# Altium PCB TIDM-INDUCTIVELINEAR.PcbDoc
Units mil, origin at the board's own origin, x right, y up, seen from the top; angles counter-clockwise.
Board outline 3600 x 4300 mil, 4 copper layers (Top Layer, Mid-Layer 1, Mid-Layer 2, Bottom Layer), stack 61.2 mil thick; 31 components, 29 nets, 126 pads, 28 vias.
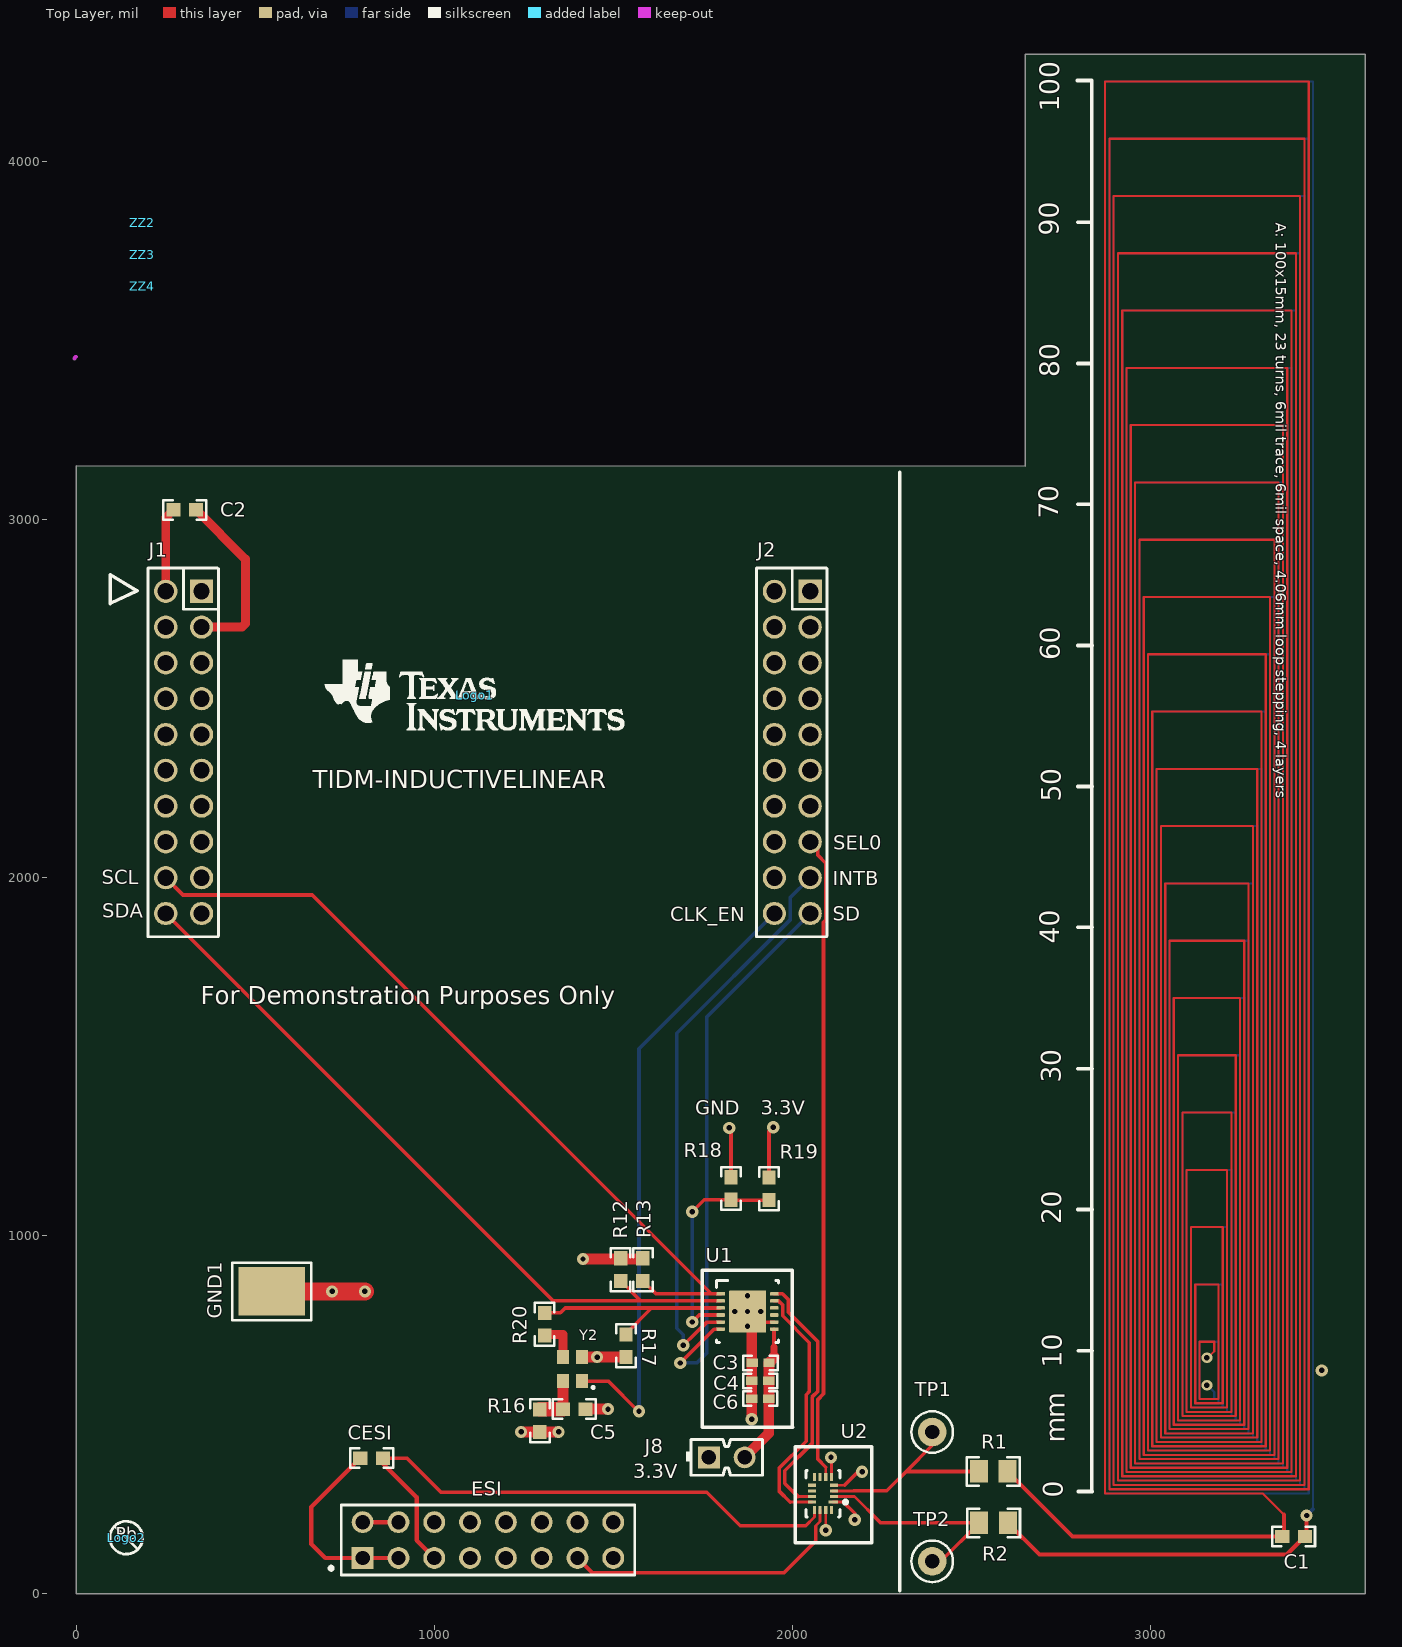
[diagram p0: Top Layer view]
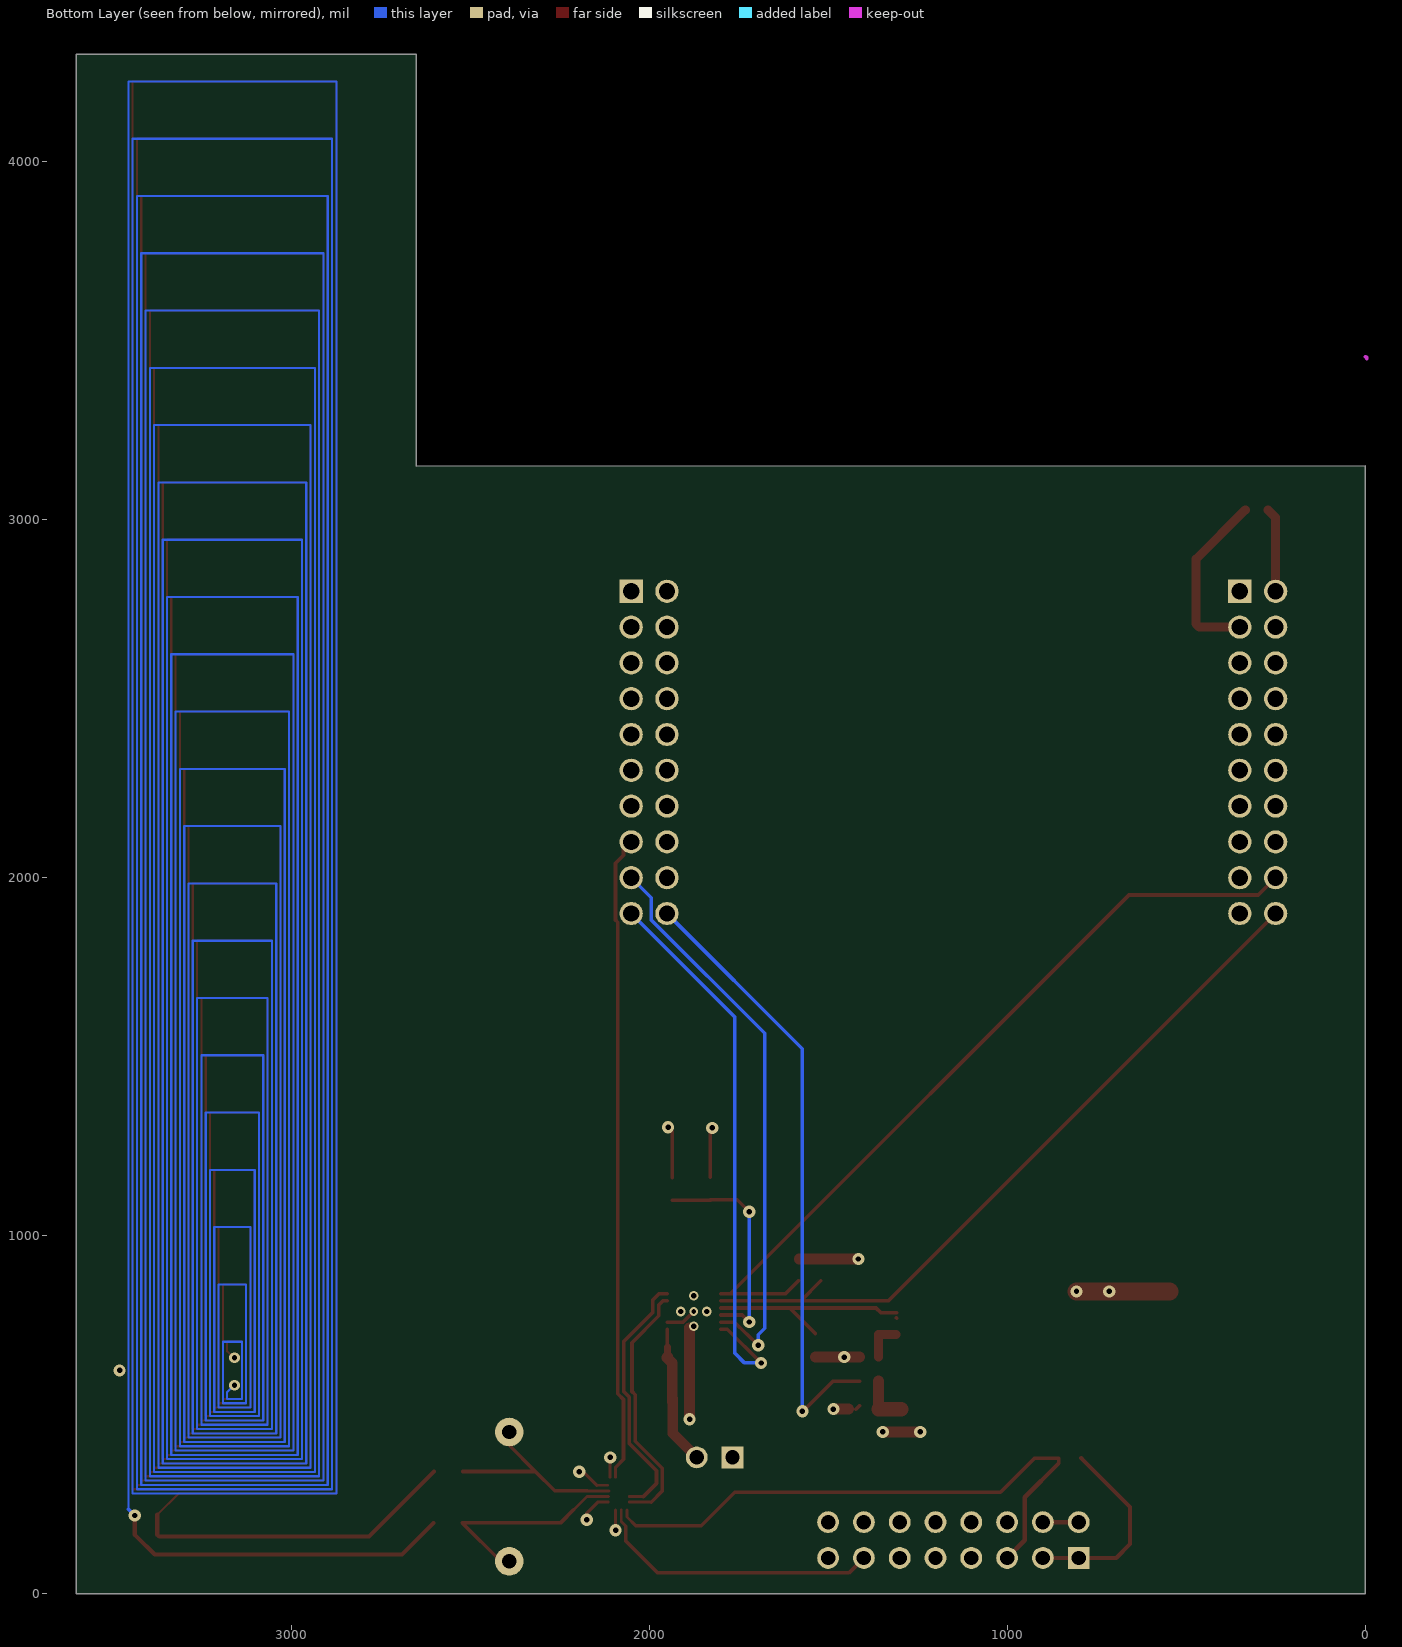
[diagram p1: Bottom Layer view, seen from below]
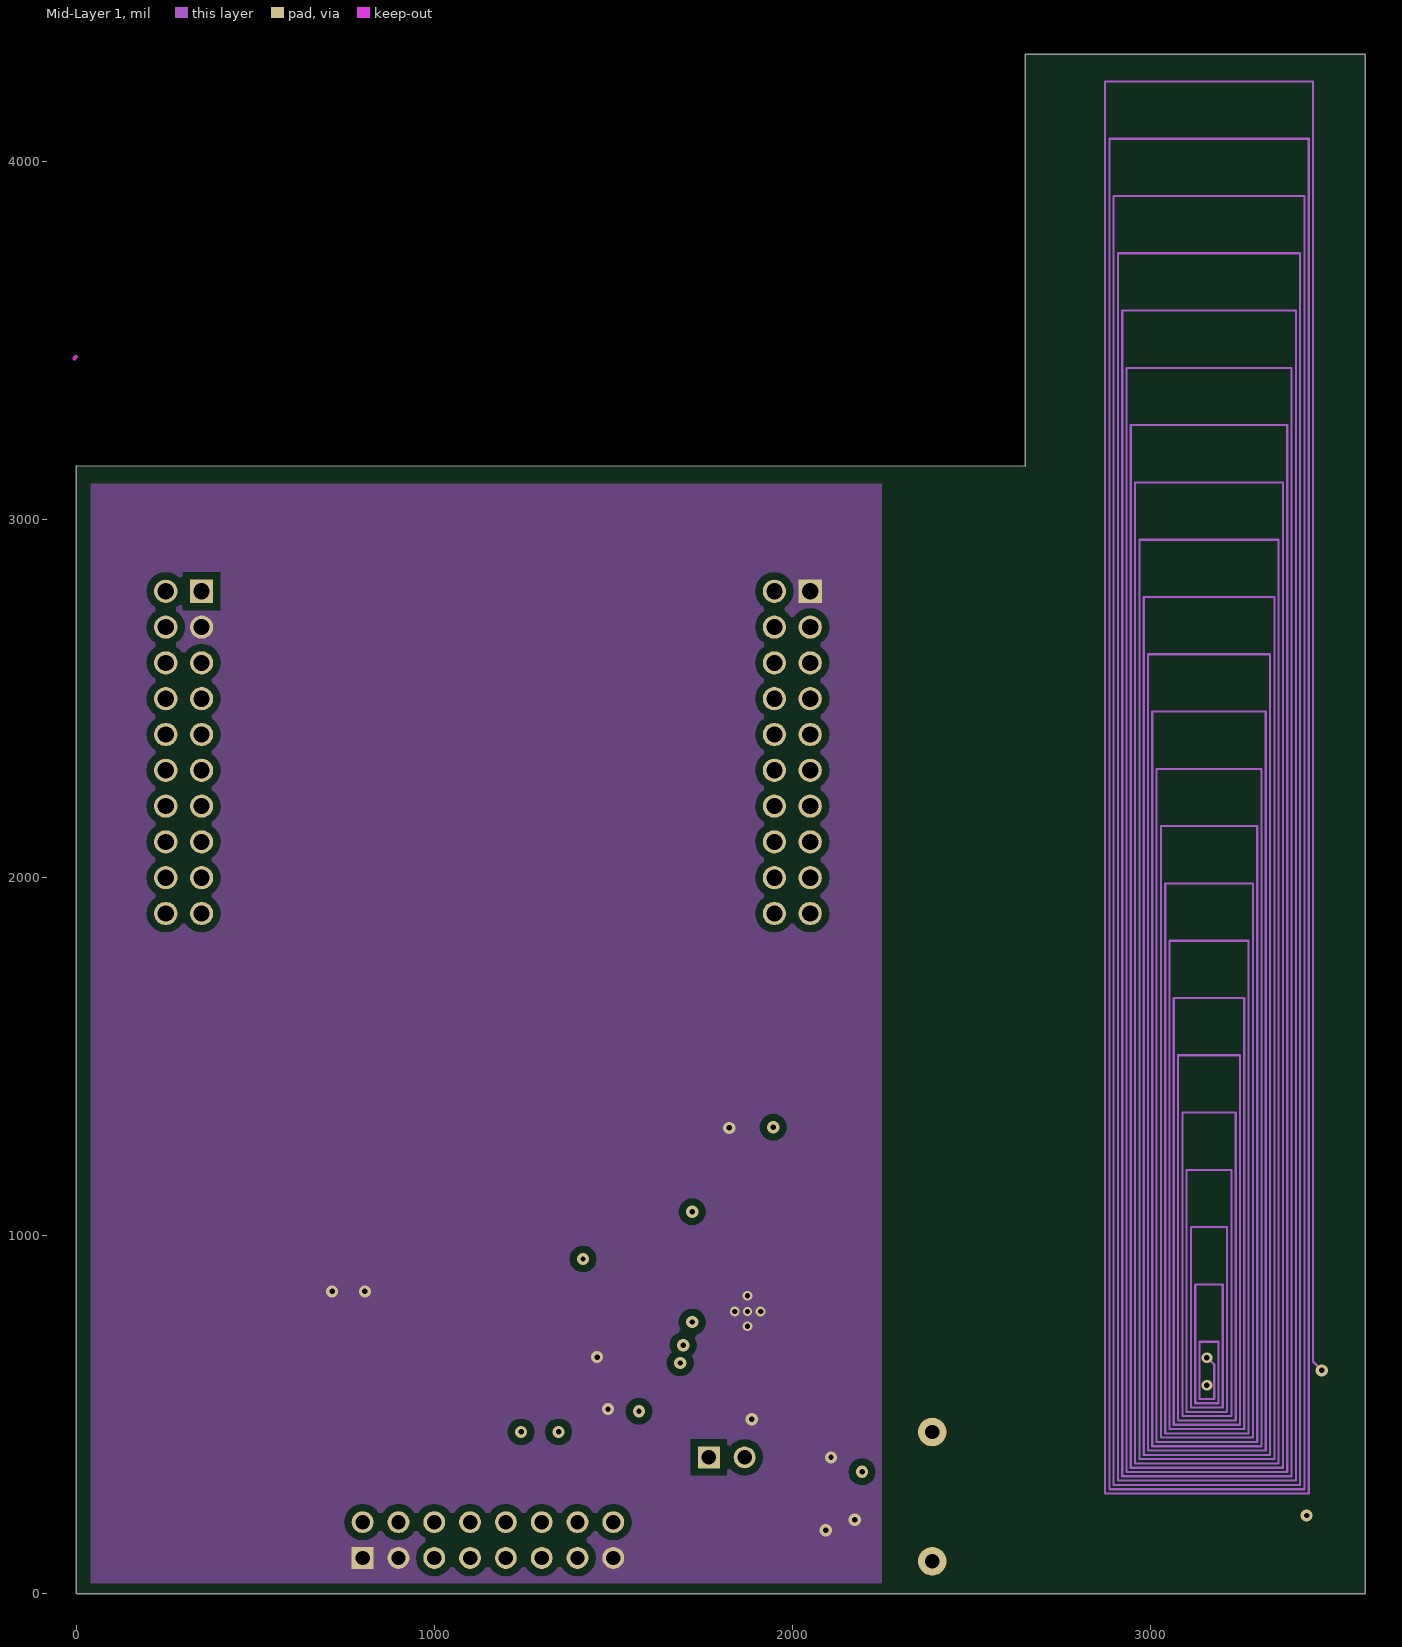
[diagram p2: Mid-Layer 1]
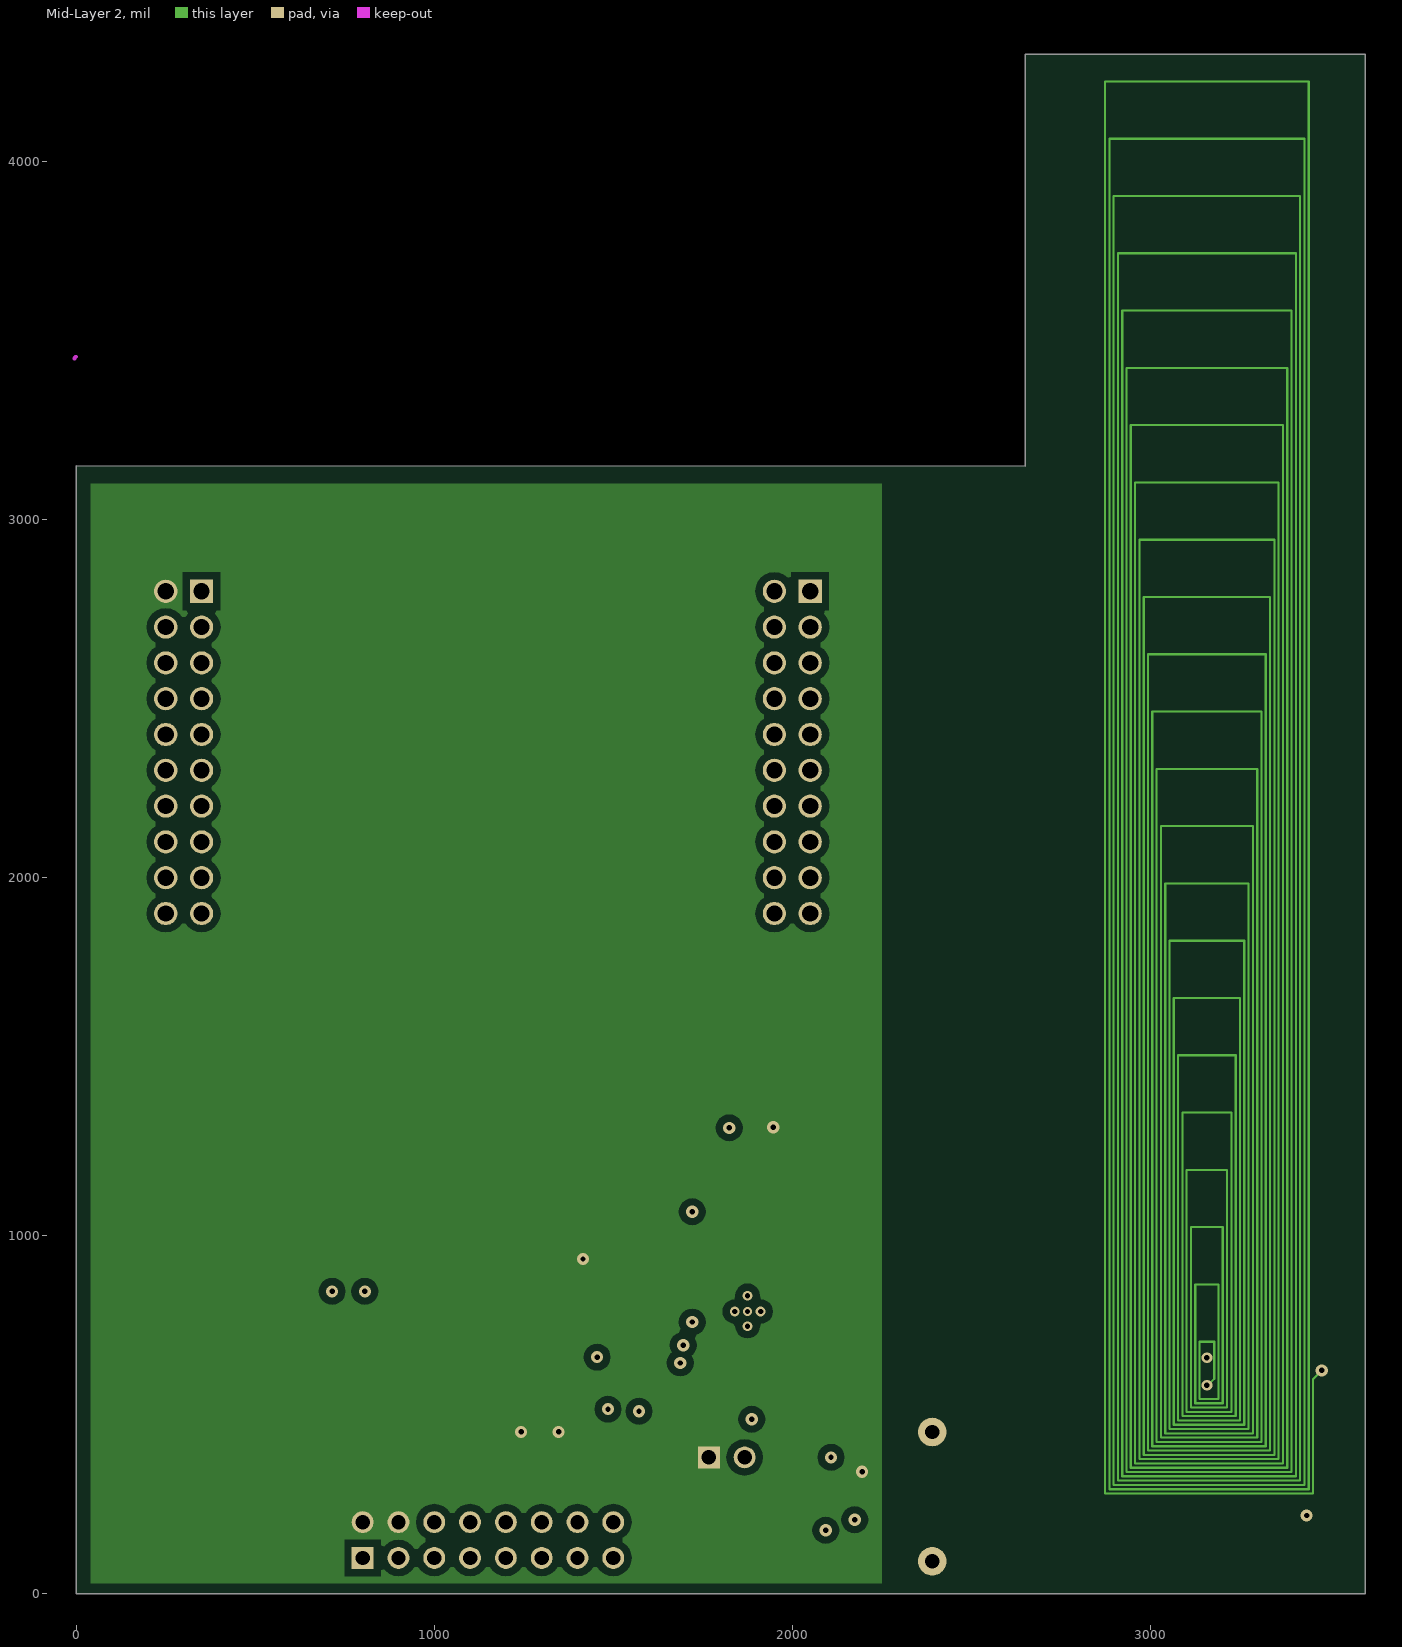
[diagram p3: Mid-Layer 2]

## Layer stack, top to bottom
Top Solder: solder mask 0.4, Solder Resist, Dk 3.5
Top Layer: signal copper 1.4
Dielectric1: core 12.6, FR-4, Dk 4.8
Mid-Layer 1: signal copper 1.4
Dielectric2: prepreg 30.4, FR-4, Dk 4.2
Mid-Layer 2: signal copper 1.4
Dielectric3: core 12.6, FR-4, Dk 4.2
Bottom Layer: signal copper 1.4
Bottom Solder: solder mask 0.4, Solder Resist, Dk 3.5

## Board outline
0,0 3600,0 3600,4300 2650,4300 2650,3149.61 0,3150

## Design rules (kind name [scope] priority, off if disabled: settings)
AcuteAngle [All] p1: minimum=4.50000000000000E+0001 checktracksonly=FALSE
AssemblyTestPointUsage [All] p1: valid=2
Clearance Clearance_Keepouts [((IsTrack Or IsArc) And Not InPoly) And IsFree and IsKeepOut vs ((IsTrack Or IsArc) And Not InPoly) And IsFree and IsKeepOut] p1: gap=0
Clearance Clearance_BoardEdge_MountingHoles [OnCopper and InComponentClass('Mounting Holes') vs IsKeepOut] p2: gap=40
Clearance Clearance_BoardEdge_Poly [OnCopper and InPoly vs IsKeepOut] p3: gap=25
Clearance Clearance_BoardEdge [OnCopper and Not InComponentClass('Logo') and not InComponentClass('FiducialMark') and not InRegion(1000,500,4000,800) and Not IsKeepout vs IsKeepOut] p4: gap=20
Clearance Clearance_Poly [InPolygon] p5: gap=20
Clearance [All] p6: gap=6.3
ComponentClearance ComponentClearance_MountingHoles_FiducialMarks [InComponentClass('Mounting Holes') vs InComponentClass('FiducialMark')] p1: gap=50 collisioncheckmode=3 verticalgap=10 showdistances=FALSE
ComponentClearance ComponentClearance_Shunt [InComponentClass('Header') vs InComponentClass('Shunt')] p2: gap=0 collisioncheckmode=3 verticalgap=0 showdistances=FALSE
ComponentClearance ComponentClearance_Logo [InComponentClass('Logo')] p3: gap=50 collisioncheckmode=3 verticalgap=10 showdistances=FALSE
ComponentClearance ComponentClearance_ScrewToNut [(HasFootprint('NY PMS 440 0025 PH')) vs (HasFootprint('Keystone_1902C'))] p4: gap=5 collisioncheckmode=3 verticalgap=10 showdistances=FALSE
ComponentClearance ComponentClearance_MountingHoles [InComponentClass('Mounting Holes')] p5: gap=250 collisioncheckmode=3 verticalgap=100000 showdistances=FALSE
ComponentClearance ComponentClearance_SmallPassives [HasFootprint('0201*') or HasFootprint('0402*') or HasFootprint('0508') or HasFootprint('0603*') or HasFootprint('0612') or HasFootprint('0805*') or HasFootprint('0815*') or HasFootprint('0830*') or HasFootprint('1206*') or HasFootprint('1210*') or HasFootprint('1808*') or HasFootprint('1812*') or HasFootprint('1825*') or HasFootprint('2010*') or HasFootprint('2220*') or HasFootprint('2225*') or HasFootprint('2512*') or HasFootprint('2728*') or HasFootprint('3518*') vs HasFootprint('0201*') or HasFootprint('0402*') or HasFootprint('0508') or HasFootprint('0603*') or HasFootprint('0612') or HasFootprint('0805*') or HasFootprint('0815*') or HasFootprint('0830*') or HasFootprint('1206*') or HasFootprint('1210*') or HasFootprint('1808*') or HasFootprint('1812*') or HasFootprint('1825*') or HasFootprint('2010*') or HasFootprint('2220*') or HasFootprint('2225*') or HasFootprint('2512*') or HasFootprint('2728*') or HasFootprint('3518*')] p6: gap=20 collisioncheckmode=3 verticalgap=10 showdistances=FALSE
ComponentClearance ComponentClearance_THtoSMT [IsThruComponent vs IsSMTComponent] p7: gap=100 collisioncheckmode=3 verticalgap=30 showdistances=FALSE
ComponentClearance ComponentClearance_THtoTH [IsThruComponent vs IsThruComponent] p8: gap=118.11 collisioncheckmode=3 verticalgap=30 showdistances=FALSE
ComponentClearance [All] p9: gap=40 collisioncheckmode=3 verticalgap=10 showdistances=FALSE
DiffPairsRouting [All] p1: maxlimit=100 minlimit=10 mostfreqgap=10 toplayer_minwidth=15 toplayer_maxwidth=15 toplayer_prefwidth=15 midlayer1_minwidth=15 midlayer1_maxwidth=15 midlayer1_prefwidth=15 midlayer2_minwidth=15 midlayer2_maxwidth=15 midlayer2_prefwidth=15 bottomlayer_minwidth=15 bottomlayer_maxwidth=15 bottomlayer_prefwidth=15 maxuncoupledlength=1000
FabricationTestPointUsage TestPointUsage [All] p1: valid=2 allowmultiple=FALSE
FabricationTestpoint Testpoint [All] p1: side=3 testpointundercomponent=TRUE minsize=40 maxsize=100 preferedsize=60 minholesize=0 maxholesize=40 preferedholesize=32 testpointgrid=1 allowsidetop=TRUE allowsidebottom=TRUE usegrid=TRUE gridtolerance=0.01
FanoutControl Fanout_LCC [IsLCC] p1: bgadir=Out bgaviamode=Centered fanoutstyle=Auto fanoutdirection=Alternating viagrid=1 // Fanout_LCC (Default Rule)
FanoutControl Fanout_BGA [IsBGA] p2: bgadir=Out bgaviamode=Centered fanoutstyle=Auto fanoutdirection=Alternating viagrid=1 // Fanout_BGA (Default Rule)
FanoutControl Fanout_Default [All] p4: bgadir=Out bgaviamode=Centered fanoutstyle=Auto fanoutdirection=Alternating viagrid=1 // Fanout_Default (Default Rule)
FanoutControl Fanout_Small [(CompPinCount < 5)] p5: bgadir=Out bgaviamode=Centered fanoutstyle=Auto fanoutdirection=OutThenIn viagrid=1 // Fanout_Small (Default Rule)
HoleSize [All] p1: absolutevalues=TRUE maxlimit=251 minlimit=8 maxpercent=80.000 minpercent=20.000
MinimumAnnularRing MinimumAnnularRing_ThermalPadVias [IsVia and InAnyComponent] p1: minimumring=5.91
MinimumAnnularRing [All] p2: minimumring=7.5
MinimumSolderMaskSliver MinimumSolderMaskSliver_Logo [InComponentClass('Logo') vs InComponentClass('Logo')] p1: minsoldermaskwidth=0.7
MinimumSolderMaskSliver [All] p2: minsoldermaskwidth=2
PlaneConnect [All] p1: planeconnectstyle=Direct reliefexpansion=10 reliefentries=4 reliefconductorwidth=10 reliefairgap=10
PolygonConnect [All] p1: connectstyle=Direct reliefconductorwidth=10 reliefentries=4 polygonreliefangle="90 Angle" airgapwidth=10
RoutingVias ThermalPadVias [IsVia and InAnyComponent] p1: holewidth=7.87 width=19.68 viastyle="Through Hole" minholewidth=7.87 minwidth=19.68 maxholewidth=12.99 maxwidth=23.62
RoutingVias [All] p2: holewidth=16 width=34 viastyle="Through Hole" minholewidth=7.87 minwidth=26 maxholewidth=40 maxwidth=65
SilkToBoardRegionClearance [Not ((IsComment or IsDesignator) And (Hide <> 'False')) and not InRegion(1000,500,4000,800)] p1:
SilkToSilkClearance SilkToSilkClearance_Pb-FreeLogo [(HasFootprint('Pb-Free_Overlay_Medium') OR HasFootprint('Pb-Free_Overlay_Small')) vs (HasFootprint('Pb-Free_Overlay_Medium') OR HasFootprint('Pb-Free_Overlay_Small'))] p1: silktosilkclearance=0
SilkToSilkClearance [All] p2: silktosilkclearance=4
SilkToSolderMaskClearance "Silk to Solder Mask Opening" [All] p1: minsilkscreentomaskgap=4 clearancetoexposedcopper=FALSE
SolderMaskExpansion [All] p1: expansion=2
UnpouredPolygon [All] p1: allowunpoured=FALSE
Width [All] p1: maxlimit=100 minlimit=6 preferedwidth=10 checkconnectedcopper=TRUE
14 further rules are at their usual default settings.

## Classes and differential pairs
component class BlankSheet: C1 C2 C3 C4 C5 C6 CESI ESI GND1 J1 J2 J8 R1 R2 R12 R13 R16 R17 R18 R19 R20 TP1 TP2 U1 U2 Y2
component class Logo: Logo1
component class TID_Hardware: Logo1 Logo2 ZZ2 ZZ3 ZZ4
component class AssemblyNote: ZZ2 ZZ3 ZZ4
component class Header: J8

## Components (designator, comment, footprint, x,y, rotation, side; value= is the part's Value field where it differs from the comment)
C1 "GRM1885C2A151JA01D" 0603 3400,160 r0 top
C2 "C0603C225K8PACTU" 0603 303.15,3027.56 r0 top
C3 "C1005X7R1C103K" 0402 1911.42,644.69 r180 top
C4 "GRM155R71C104JA88D" 0402 1910.43,594.49 r180 top
C5 "C1608C0G1E103J" 0603 1390.8,515.49 r0 top
C6 "GRM155R61A105KE15D" 0402 1910.43,545.28 r180 top
CESI "GRM188R61A474KA61D" 0603 824.8,378.94 r180 top
ESI "SSQ-108-02-G-D" SAMTEC_SSQ-108-02-G-D 1150,150 r0 top
GND1 "5016" Testpoint_Keystone_Compact 546.26,844.49 r180 top
J1 "SSW-110-23-F-D" CONN_SSW-110-23-F-D 300,2350 r90 top
J2 "SSW-110-23-F-D" CONN_SSW-110-23-F-D 2000,2350 r90 top
J8 "TSW-102-07-T-S" Samtec_TSW-102-07-T-S 1816.93,380.91 r0 top
Logo1 "Texas Instruments" TI_Stacked_Overlay_Small 1112.77,2509.97 r0 top
Logo2 "Pb-Free Symbol" Pb-Free_Overlay_Small 139.76,156.5 r0 top
R1 "ERJ-6GEY0R00V" 0805_HV 2561.02,341.53 r180 top
R2 "ERJ-6GEY0R00V" 0805_HV 2562.01,197.83 r180 top
R12 "RC0603FR-074K7L" 0603 1520.67,905.51 r90 top
R13 "RC0603FR-074K7L" 0603 1582.68,905.51 r90 top
R16 "CRCW06030000Z0EA" 0603 1294.8,483.49 r270 top
R17 "CRCW06030000Z0EA" 0603 1535.43,692.91 r270 top
R18 "CRCW06030000Z0EA" 0603 1828.74,1131.89 r90 top
R19 "CRCW06030000Z0EA" 0603 1935.04,1130.91 r90 top
R20 "CRCW06030000Z0EA" 0603 1308.07,752.95 r90 top
TP1 "5000" Keystone5000 2390.75,451.77 r0 top
TP2 "5000" Keystone5000 2390.75,90.55 r0 top
U1 "LDC1612DNT" DNT0012B 1875,788.39 r0 top
U2 "FSUSB74" LCCS40P210X290X55-16N 2085.63,279.53 r180 top
Y2 "625L3C040M00000" OSC_CTS_625 1385.79,627.49 r180 top
ZZ2 "These assemblies are ESD sensitive, ESD precautions shall be observed." AssemblyNote 185,3829.11 r0 top
ZZ3 "These assemblies must be clean and free from flux and all contaminants. Use of no clean flux is not acceptable." AssemblyNote 185,3740.56 r0 top
ZZ4 "These assemblies must comply with workmanship standards IPC-A-610 Class 2, unless otherwise specified." AssemblyNote 185,3652 r0 top

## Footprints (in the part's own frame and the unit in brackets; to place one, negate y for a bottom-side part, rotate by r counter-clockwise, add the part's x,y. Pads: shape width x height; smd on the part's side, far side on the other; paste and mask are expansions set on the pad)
0402 [mm] "0402 from SM-752 data"
  rect 0.8x0.6 smd: 1(-0.6,0) 2(0.6,0)
  silkscreen extent -1.22,-0.52 1.22,0.52, body extent -0.55,-0.3 0.55,0.3, height 0.6
0603 [mm] "0603 from SM-752 data"
  rect 1x0.95 smd: 1(-0.8,0) 2(0.8,0)
  silkscreen extent -1.52,-0.69 1.52,0.69, body extent -0.87,-0.47 0.87,0.47, height 0.85
0805_HV [mil] "0805 with 30mil clearance between pads"
  rect 50x63 smd: 1(-40,0) 2(40,0)
  silkscreen extent -74,-40 74,40, body extent -43,-29 43,29, height 57
AssemblyNote [mil] "Assembly Note"
CONN_SSW-110-23-F-D [mm] "SAMTEC"
  rect 1.65x1.65 hole 1.15: 1(11.43,-1.27)
  round 1.65 hole 1.15: 2(11.43,1.27) 3(8.89,-1.27) 4(8.89,1.27) 5(6.35,-1.27) 6(6.35,1.27) 7(3.81,-1.27) 8(3.81,1.27) 9(1.27,-1.27) 10(1.27,1.27) 11(-1.27,-1.27) 12(-1.27,1.27) 13(-3.81,-1.27) 14(-3.81,1.27) 15(-6.35,-1.27) 16(-6.35,1.27) 17(-8.89,-1.27) 18(-8.89,1.27) 19(-11.43,-1.27) 20(-11.43,1.27)
  silkscreen extent -13.08,-2.46 13.08,2.54, body extent -13,-2.51 13,2.54, height 8.59
DNT0012B [mm] "SON, 12-Leads, Body 4x4mm, Pitch 0.5mm"
  rrect40% 0.6x0.25 smd: 1(-1.9,1.25) 2(-1.9,0.75) 3(-1.9,0.25) 4(-1.9,-0.25) 5(-1.9,-0.75) 6(-1.9,-1.25) 7(1.9,-1.25) 8(1.9,-0.75) 9(1.9,-0.25) 10(1.9,0.25) 11(1.9,0.75) 12(1.9,1.25)
  rrect4% 2.6x3 smd paste-1.3: 13(0,0)
  silkscreen extent -2.2,-2.2 2.2,2.2, body extent -2.05,-2.05 2.05,2.05, height 0.81
Keystone5000 [mil] "For Keystone 500x miniature loop terminals"
  round 80 hole 40: 1(0,0)
  silkscreen extent -58,-58 58,58, body extent -49,-49 49,49, height 182
LCCS40P210X290X55-16N [mm] "LCC, 16-Pins, Body 2.10x2.90mmx0.55mm, Pitch 0.40mm, IPC Medium Density"
  rect 0.663x0.225 smd: 1(-0.719,0.6)
  rect 0.563x0.225 smd: 2(-0.769,0.2) 3(-0.769,-0.2) 4(-0.769,-0.6) 9(0.769,-0.6) 10(0.769,-0.2) 11(0.769,0.2) 12(0.769,0.6)
  rect 0.225x0.563 smd: 5(-0.6,-1.168) 6(-0.2,-1.168) 7(0.2,-1.168) 8(0.6,-1.168) 13(0.6,1.169) 14(0.2,1.169) 15(-0.2,1.169) 16(-0.6,1.169)
  silkscreen extent -1.73,-1.65 1.2,1.65, body extent -1.05,-1.45 1.05,1.45, height 0.55
OSC_CTS_625 [mm] "CTS"
  rect 0.85x1 smd: 1(-0.675,0.85) 2(-0.675,-0.85) 3(0.675,-0.85) 4(0.675,0.85)
  silkscreen extent -1.53,1.25 -1.43,1.35, body extent -1.1,-1.35 1.1,1.35, height 1.02
Pb-Free_Overlay_Small [mil]
  silkscreen extent -46,-46 46,46
SAMTEC_SSQ-108-02-G-D [mm] "Receptacle, 8x2, Body 21.08x4.95mm, Pitch 2.54mm"
  rect 1.55x1.55 hole 1.02: 1(-8.89,-1.27)
  round 1.55 hole 1.02: 2(-8.89,1.27) 3(-6.35,-1.27) 4(-6.35,1.27) 5(-3.81,-1.27) 6(-3.81,1.27) 7(-1.27,-1.27) 8(-1.27,1.27) 9(1.27,-1.27) 10(1.27,1.27) 11(3.81,-1.27) 12(3.81,1.27) 13(6.35,-1.27) 14(6.35,1.27) 15(8.89,-1.27) 16(8.89,1.27)
  silkscreen extent -11.25,-2.48 10.41,2.48, body extent -10.41,-2.48 10.41,2.48, height 21.95
Samtec_TSW-102-07-T-S [mm] "Header, 2.54 mm, 2x1, Tin, TH"
  rect 1.55x1.55 hole 1.02: 1(-1.27,0)
  round 1.55 hole 1.02: 2(1.27,0)
  silkscreen extent -2.9,-1.27 2.54,1.27, body extent -2.54,-1.27 2.54,1.27, height 8.38
Testpoint_Keystone_Compact [mil] "Compact SMT test point"
  rect 185x135 smd: 1(0,0)
  silkscreen extent -110,-80 110,80, body extent -75,-56 75,56, height 91
TI_Stacked_Overlay_Small [mil]
  silkscreen extent -418,-98 418,98

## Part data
C1: "CAP, CERM, 150 pF, 100 V, +/- 5%, C0G/NP0, 0603"
C2: "CAP, CERM, 2.2uF, 10V, +/-10%, X5R, 0603"
C3: "CAP, CERM, 0.01 µF, 16 V, +/- 10%, X7R, 0402"
C4: library part 0402YC132KAT2A, "CAP CER 0.1UF 16V 5% X7R 0402"
C5: "CAP, CERM, 0.01uF, 25V, +/-5%, C0G/NP0, 0603"
C6: "CAP, CERM, 1uF, 10V, +/-10%, X5R, 0402"
CESI: "CAP, CERM, 0.47 µF, 10 V, +/- 10%, X5R, 0603"
ESI: "Receptacle, 100mil, 8x2, Gold, TH"
GND1: "Test Point, Compact, SMT"
J1 J2: "Connector, Receptacle, 100mil, 10x2, Gold plated, TH"
J8: "Header, 2.54 mm, 2x1, Tin, TH"
Logo1: library part TI_Logo, "Texas Instrument Corporate Signature"
Logo2: library part Pb-Free
R1 R2: "RES, 0, 5%, 0.125 W, 0805"
R12 R13: "RES, 4.70k ohm, 1%, 0.1W, 0603"
R16 R17 R18 R19 R20: "RES, 0 ohm, 5%, 0.1W, 0603"
TP1 TP2: "Test Point, Miniature, Red, TH"
U1: "Multi-Channel 12/28-Bit Inductance to Digital Converter with I2C, DNT0012B"
U2: "MUX"
Y2: "OSC, 40 MHz, 3.3 V, SMD"
ZZ2 ZZ3 ZZ4: library part AssemblyNote

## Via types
v1: diameter 34, hole 15, Top Layer to Bottom Layer, tented both sides, 20 vias
v2: diameter 27, hole 15, Top Layer to Bottom Layer, tented both sides, 4 vias
v3: diameter 30, hole 15, Top Layer to Bottom Layer, tented both sides, 2 vias
v4: diameter 24, hole 13, Top Layer to Bottom Layer, 1 vias
v5: diameter 34, hole 15, Top Layer to Bottom Layer, 1 vias

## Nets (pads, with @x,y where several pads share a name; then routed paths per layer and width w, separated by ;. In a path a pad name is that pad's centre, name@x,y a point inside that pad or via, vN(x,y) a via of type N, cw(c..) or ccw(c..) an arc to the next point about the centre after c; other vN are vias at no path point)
+3.3V: C2.1 ESI.2 ESI.4 J1.2 J8.1 R12.2 R13.2 R16.2 R19.2 U2.4 | length 849.5
  Top Layer w8: U2.4 2146.04,303.15
  Top Layer w10: R13.2@1580.71,935.04 R13.2 ; R19.2 1935.04,1291.34 v1(1946.85,1303.15) ; 2146.04,303.15 2183.44,340.55 v1(2194.88,340.55)
  Top Layer w12: ESI.2 ESI.4
  Top Layer w25: J1.2 250,3005.91 C2.1
  Top Layer w30: v5(1242.44,452) R16.2 v1(1347.16,452) ; v1(1415.35,935.04) R13.2@1580.71,935.04
CLK_EN: J2.20 Y2.1 | length 1741.1
  Top Layer w10: Y2.1 1485.7,594.02 1569.88,509.84 v1(1571.85,509.84)
  Bottom Layer w10: v1(1571.85,509.84) 1571.85,1521.85 J2.20
CLK_OUT: R20.1 Y2.3 | length 112.2
  Top Layer w25: R20.1@1310.21,724.15 1359.21,724.15 Y2.3
COIL: C1.1 C1.2 R1.1 R2.1 | length 436694.3
  Top Layer w6: v3@3160,659 3178.5,677.5 3178.5,704 3137.5,704 3137.5,544 3190.5,544 3190.5,864 3125.5,864 3125.5,532 3202.5,532 3202.5,1024 3113.5,1024 3113.5,520 3214.5,520 3214.5,1184 3101.5,1184 3101.5,508 3226.5,508 3226.5,1344 3089.5,1344 3089.5,496 3238.5,496 3238.5,1504 3077.5,1504 3077.5,484 3250.5,484 3250.5,1664 3065.5,1664 3065.5,472 3262.5,472 3262.5,1824 3053.5,1824 3053.5,460 3274.5,460 3274.5,1984 3041.5,1984 3041.5,448 3286.5,448 3286.5,2144 3029.5,2144 3029.5,436 3298.5,436 3298.5,2304 3017.5,2304 3017.5,424 3310.5,424 3310.5,2464 3005.5,2464 3005.5,412 3322.5,412 3322.5,2624 2993.5,2624 2993.5,400 3334.5,400 3334.5,2784 2981.5,2784 2981.5,388 3346.5,388 3346.5,2944 2969.5,2944 2969.5,376 3358.5,376 3358.5,3104 2957.5,3104 2957.5,364 3370.5,364 3370.5,3264 2945.5,3264 2945.5,352 3382.5,352 3382.5,3424 2933.5,3424 2933.5,340 3394.5,340 3394.5,3584 2921.5,3584 2921.5,328 3406.5,328 3406.5,3744 2909.5,3744 2909.5,316 3418.5,316 3418.5,3904 2897.5,3904 2897.5,304 3430.5,304 3430.5,4064 2885.5,4064 2885.5,292 3442.5,292 3442.5,4224 2873.5,4224 2873.5,280 3314,280 3373.5,220.5
  Top Layer w12: R1.1 2782.56,160 C1.1 ; R2.1 2690.43,109.41 3380.91,109.41 C1.2 ; C1.1@3373.5,165 3373.5,220.5 ; C1.2@3436.5,165 v1(3436.5,218.5)
  Mid-Layer 1 w6: v3@3160,659 3178.5,640.5 3178.5,544 3137.5,544 3137.5,704 3190.5,704 3190.5,532 3125.5,532 3125.5,864 3202.5,864 3202.5,520 3113.5,520 3113.5,1024 3214.5,1024 3214.5,508 3101.5,508 3101.5,1184 3226.5,1184 3226.5,496 3089.5,496 3089.5,1344 3238.5,1344 3238.5,484 3077.5,484 3077.5,1504 3250.5,1504 3250.5,472 3065.5,472 3065.5,1664 3262.5,1664 3262.5,460 3053.5,460 3053.5,1824 3274.5,1824 3274.5,448 3041.5,448 3041.5,1984 3286.5,1984 3286.5,436 3029.5,436 3029.5,2144 3298.5,2144 3298.5,424 3017.5,424 3017.5,2304 3310.5,2304 3310.5,412 3005.5,412 3005.5,2464 3322.5,2464 3322.5,400 2993.5,400 2993.5,2624 3334.5,2624 3334.5,388 2981.5,388 2981.5,2784 3346.5,2784 3346.5,376 2969.5,376 2969.5,2944 3358.5,2944 3358.5,364 2957.5,364 2957.5,3104 3370.5,3104 3370.5,352 2945.5,352 2945.5,3264 3382.5,3264 3382.5,340 2933.5,340 2933.5,3424 3394.5,3424 3394.5,328 2921.5,328 2921.5,3584 3406.5,3584 3406.5,316 2909.5,316 2909.5,3744 3418.5,3744 3418.5,304 2897.5,304 2897.5,3904 3430.5,3904 3430.5,292 2885.5,292 2885.5,4064 3442.5,4064 3442.5,280 2873.5,280 2873.5,4224 3454.5,4224 3454.5,648.5 v1(3479,624)
  Mid-Layer 2 w6: v3@3160,582 3178.5,600.5 3178.5,704 3137.5,704 3137.5,544 3190.5,544 3190.5,864 3125.5,864 3125.5,532 3202.5,532 3202.5,1024 3113.5,1024 3113.5,520 3214.5,520 3214.5,1184 3101.5,1184 3101.5,508 3226.5,508 3226.5,1344 3089.5,1344 3089.5,496 3238.5,496 3238.5,1504 3077.5,1504 3077.5,484 3250.5,484 3250.5,1664 3065.5,1664 3065.5,472 3262.5,472 3262.5,1824 3053.5,1824 3053.5,460 3274.5,460 3274.5,1984 3041.5,1984 3041.5,448 3286.5,448 3286.5,2144 3029.5,2144 3029.5,436 3298.5,436 3298.5,2304 3017.5,2304 3017.5,424 3310.5,424 3310.5,2464 3005.5,2464 3005.5,412 3322.5,412 3322.5,2624 2993.5,2624 2993.5,400 3334.5,400 3334.5,2784 2981.5,2784 2981.5,388 3346.5,388 3346.5,2944 2969.5,2944 2969.5,376 3358.5,376 3358.5,3104 2957.5,3104 2957.5,364 3370.5,364 3370.5,3264 2945.5,3264 2945.5,352 3382.5,352 3382.5,3424 2933.5,3424 2933.5,340 3394.5,340 3394.5,3584 2921.5,3584 2921.5,328 3406.5,328 3406.5,3744 2909.5,3744 2909.5,316 3418.5,316 3418.5,3904 2897.5,3904 2897.5,304 3430.5,304 3430.5,4064 2885.5,4064 2885.5,292 3442.5,292 3442.5,4224 2873.5,4224 2873.5,280 3454.5,280 3454.5,599.5 v1(3479,624)
  Bottom Layer w6: v3@3160,582 3178.5,563.5 3178.5,544 3137.5,544 3137.5,704 3190.5,704 3190.5,532 3125.5,532 3125.5,864 3202.5,864 3202.5,520 3113.5,520 3113.5,1024 3214.5,1024 3214.5,508 3101.5,508 3101.5,1184 3226.5,1184 3226.5,496 3089.5,496 3089.5,1344 3238.5,1344 3238.5,484 3077.5,484 3077.5,1504 3250.5,1504 3250.5,472 3065.5,472 3065.5,1664 3262.5,1664 3262.5,460 3053.5,460 3053.5,1824 3274.5,1824 3274.5,448 3041.5,448 3041.5,1984 3286.5,1984 3286.5,436 3029.5,436 3029.5,2144 3298.5,2144 3298.5,424 3017.5,424 3017.5,2304 3310.5,2304 3310.5,412 3005.5,412 3005.5,2464 3322.5,2464 3322.5,400 2993.5,400 2993.5,2624 3334.5,2624 3334.5,388 2981.5,388 2981.5,2784 3346.5,2784 3346.5,376 2969.5,376 2969.5,2944 3358.5,2944 3358.5,364 2957.5,364 2957.5,3104 3370.5,3104 3370.5,352 2945.5,352 2945.5,3264 3382.5,3264 3382.5,340 2933.5,340 2933.5,3424 3394.5,3424 3394.5,328 2921.5,328 2921.5,3584 3406.5,3584 3406.5,316 2909.5,316 2909.5,3744 3418.5,3744 3418.5,304 2897.5,304 2897.5,3904 3430.5,3904 3430.5,292 2885.5,292 2885.5,4064 3442.5,4064 3442.5,280 2873.5,280 2873.5,4224 3454.5,4224 3454.5,236.51
  Bottom Layer w10: v1(3436.5,218.5) 3454.5,236.51
  other v3: 3158.03,582 3158.03,659
ESICH0/ESITEST0: ESI.14
ESICH1/ESITEST1: ESI.13 U2.14 | length 810.9
  Top Layer w8: 2065.2,188.89 2077.76,201.44 U2.14
  Top Layer w10: ESI.13 1441.81,58.19 1976.18,58.19 2065.2,147.21 2065.2,188.89
ESICH2/ESITEST2: ESI.12
ESICH3/ESITEST3: ESI.11
ESICI: ESI.6
ESICI0: ESI.10
ESICI1: ESI.9
ESICI2: ESI.8
ESICI3: ESI.7
ESICOM: CESI.1 ESI.5 U2.13 | length 1651.6
  Top Layer w8: 2037.4,189.96 2062.01,214.57 U2.13
  Top Layer w10: CESI.1@856.3,364.17 CESI.1 923.23,378.94 1018.7,283.46 1760.83,283.46 1854.33,189.96 2037.4,189.96
  Top Layer w12: CESI.1@856.3,364.17 950.79,269.69 950.79,149.21 ESI.5
ESITEST4: ESI.16
GND: C2.2 C3.2 C4.2 C5.2 C6.2 CESI.2 ESI.1 ESI.3 ESI.15 GND1.1 J1.3 J2.1 R17.2 R18.2 U1.8 U1.13 U2.1 U2.5 U2.15 Y2.2 | length 2161.5
  Top Layer w8: v1@2093.51,189.96 U2.15 ; U2.5 v1@2109.25,379.92 ; U2.1 2143.09,255.9
  Top Layer w10: C5.2@1412.36,525.43 C5.2 ; R17.2@1534.97,660.95 R17.2 ; v1(1823.82,1301.18) 1828.74,1296.26 R18.2 ; v4(1875,788.39) 1904.53,758.86 U1.8 ; v1(2108.27,380.91) v1@2109.25,379.92 ; 2143.09,255.9 2174.21,224.78 v1(2174.21,206.69)
  Top Layer w12: CESI.2 656.5,242.13 656.5,138.78 695.28,100 ESI.1 ESI.3
  Top Layer w25: C2.2 472.44,2889.76 472.44,2709.65 462.8,2700 J1.3
  Top Layer w30: Y2.2 v1(1454.75,660.95) R17.2@1534.97,660.95 ; 1442.85,515.75 v1(1485.24,515.75) ; v1(1886.81,487.2) C6.2 C4.2 ; C4.2@1886.81,603.35 U1.13@1886.81,742.73
  Top Layer w50: GND1.1 v1(714.57,844.49) 767.72,844.49 v1(806.1,844.49)
  other v1: 2093.51,177.16
  other v2: 1875,747.05 1839,788.39 1911.42,788.39 1875,832.68
I2CSCI: J1.18 R13.1 U1.1 | length 2249.5
  Top Layer w10: J1.18 298.23,1951.77 659.45,1951.77 1773.62,837.6 1761.81,837.6 ; R13.1 1619.09,837.6 1761.81,837.6 ; U1.1 1761.81,837.6
I2CSDA: J1.20 R12.1 U1.2 | length 2077.8
  Top Layer w10: J1.20 1332.09,817.91 1576.77,817.91 ; R12.1 1576.77,817.91 ; U1.2 1738.19,817.91 1576.77,817.91
IN1A: U1.11 U2.12 | length 718.7
  Top Layer w8: 1994.1,255.9 U2.12
  Top Layer w10: U1.11 1961.68,817.91 1972.91,806.68 1972.91,776.1 2047.74,701.28 2047.74,564.88 2038.98,556.13 2038.98,426.2 1963.03,350.26 1963.03,286.97 1994.1,255.9
IN1B: U1.12 U2.11 | length 722
  Top Layer w8: 2015.75,271.65 U2.11
  Top Layer w10: U1.12 1972.44,837.6 1989.21,820.83 1989.21,786.42 2070.87,704.76 2070.87,564.96 2055.28,549.37 2055.28,419.45 1979.33,343.5 1979.33,308.07 2015.75,271.65
INTB: J2.17 U1.5 | length 1600.3
  Top Layer w10: v1(1695.28,694.28) 1761.81,758.86 U1.5
  Bottom Layer w10: v1@1694.17,695.39 v1(1695.28,694.28) 1695.28,723.03 1677.17,741.14 1677.17,1565.25 1993.78,1881.87 1993.78,1943.78 J2.17
LC1: R1.2 TP1.1 U2.3 | length 571.9
  Top Layer w8: U2.3@2111.97,287.4 2172.24,287.4
  Top Layer w10: 2172.24,287.4 2263.78,287.4 2317.91,341.53 ; TP1.1 2390.75,414.37 2317.91,341.53 ; R1.2 2317.91,341.53
LC2: R2.2 TP2.1 U2.2 | length 615
  Top Layer w8: U2.2@2113.33,271.65 2173.6,271.65 2211,234.25
  Top Layer w10: 2211,234.25 2247.42,197.83 R2.2 2414.73,90.55 TP2.1
LDC_CLKIN: R17.1 R20.2 U1.3 | length 601.3
  Top Layer w10: R20.2 1352.36,784.45 1366.14,798.23 1606.3,798.23 ; R20.2@1308.59,769.77 R20.2@1310.21,771.39 ; R17.1@1535.43,726.38 1606.3,797.24 1606.3,798.23 ; U1.3 1606.3,798.23
NetC3_1: C3.1 C4.1 C6.1 J8.2 U1.7 | length 412.1
  Top Layer w10: C6.1@1927.6,538.82 C6.1 ; C4.1 C4.1@1935.04,594.49 ; 1948.82,688.98 1948.82,738.83 U1.7
  Top Layer w20: 1948.82,661.61 1948.82,688.98
  Top Layer w30: J8.2 1934.05,448.03 1934.05,503.51 C6.1 ; C6.1@1935.04,536.42 1935.04,594.49 C3.1 1949.8,659.45 1948.82,661.61
NetC5_1: C5.1 R16.1 Y2.4 | length 143.2
  Top Layer w10: R16.1 R16.1@1295.31,515.49
  Top Layer w30: Y2.4 C5.1
  Top Layer w40: R16.1@1295.31,515.49 C5.1
NetR18_1: R18.1 R19.1 U1.4 | length 625.4
  Top Layer w10: v1(1720.47,758.86) 1740.16,778.54 U1.4 ; v1(1720.47,1066.93) 1753.94,1100.39 R18.1 ; R18.1@1827.76,1099.41 R19.1
  Bottom Layer w10: v1(1720.47,758.86) v1(1720.47,1066.93)
SD: J2.19 U1.6 | length 1586.4
  Top Layer w10: v1(1687.01,644.68) 1781.5,739.17 U1.6
  Bottom Layer w10: v1@1687.01,645.99 v1(1687.01,644.68) 1733.27,644.68 1760.83,672.24 1760.83,1610.83 J2.19
SEL0: J2.15 U2.6 | length 1810.9
  Top Layer w8: U2.6 2093.51,353.35
  Top Layer w10: J2.15 2071.58,2078.42 2071.58,2062.54 2093.78,2040.34 2093.78,1881.87 2087.17,1875.25 2087.17,558.21 2071.58,542.62 2071.58,375.27 2093.51,353.35
pads on no net: J1.1 J1.4 J1.5 J1.6 J1.7 J1.8 J1.9 J1.10 J1.11 J1.12 J1.13 J1.14 J1.15 J1.16 J1.17 J1.19 J2.2 J2.3 J2.4 J2.5 J2.6 J2.7 J2.8 J2.9 J2.10 J2.11 J2.12 J2.13 J2.14 J2.16 J2.18 U1.9 U1.10 U2.7 U2.8 U2.9 U2.10 U2.16

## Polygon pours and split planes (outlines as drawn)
GND on Mid-Layer 1 "GND" (solid, pour order 10): 40,3100 2250,3100 2250,30 40,30
+3.3V on Mid-Layer 2 "Power" (solid, pour order 13): 40,3100 2250,3100 2250,30 40,30

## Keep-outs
Keep-Out Layer:
  lines w10: -5,3450 cw(c0,3450) 0,3455 ccw(c0,3450) -5,3450

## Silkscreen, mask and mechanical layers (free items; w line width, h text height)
Top Overlay:
  lines w10: 1749.02,465 1749.02,903.54 2000,903.54 ; 1750,465 2000.98,465 ; 2000,465 2000,902.56 ; 2221.46,406.5 2221.46,142.72 2007.87,142.72 2007.87,410.43 2221.46,410.43 ; 2300,8.07 2300,3131.89 ; 94.49,2765.75 94.49,2846.46 170.28,2801.18 94.49,2765.75
  lines w10.43: 2796.91,4226.75 2835.62,4226.75 ; 2797.53,3042.74 2836.34,3042.74 ; 2797.53,3436.3 2836.45,3436.3 ; 2797.53,3831.11 2836.45,3831.11 ; 2798.15,1073.19 2837.07,1073.19 ; 2798.15,1466.64 2837.07,1466.64 ; 2798.15,1861.55 2837.07,1861.55 ; 2798.15,2255.01 2837.07,2255.01 ; 2798.15,2648.56 2837.07,2648.56 ; 2798.88,285.56 2837.7,285.56 ; 2798.88,679.01 2837.7,679.01 ; 2836.45,284.93 2836.45,4225.92
  text "0" at 2764.02,4232.45 h92.06 r90
  text "0" at 2764.02,4185.83 h92.06 r90
  text "1" at 2764.02,4139.21 h92.06 r90
  text "0" at 2762.36,3840.08 h92.06 r90
  text "A: 100x15mm, 23 turns, 6mil trace, 6mil space, 4.06mm loop stepping, 4 layers" at 3350,3830 h30 r270
  text "9" at 2762.36,3793.36 h92.06 r90
  text "0" at 2764.02,3444.64 h92.06 r90
  text "8" at 2764.02,3397.93 h92.06 r90
  text "0" at 2760.69,3049.21 h92.06 r90
  text "7" at 2760.69,3002.49 h92.06 r90
  text "0" at 2765.69,2653.68 h92.06 r90
  text "6" at 2765.69,2607.06 h92.06 r90
  text "0" at 2767.35,2258.25 h92.06 r90
  text "TIDM-INDUCTIVELINEAR" at 661,2250.12 h50
  text "5" at 2767.35,2211.63 h92.06 r90
  text "SEL0" at 2114.17,2078.74 h40
  text "SCL" at 70.87,1982.28 h40
  text "INTB" at 2113.19,1979.33 h40
  text "SDA" at 72.83,1887.8 h40
  text "SD" at 2113.19,1879.92 h40
  text "CLK_EN" at 1658.46,1877.95 h40
  text "0" at 2764.02,1862.81 h92.06 r90
  text "4" at 2764.02,1816.19 h92.06 r90
  text "For Demonstration Purposes Only" at 347.44,1646.65 h50
  text "0" at 2767.35,1474.05 h92.06 r90
  text "3" at 2767.35,1427.43 h92.06 r90
  text "GND" at 1729.33,1337.6 h40
  text "3.3V" at 1911.42,1337.6 h40
  text "0" at 2769.02,1078.72 h92.06 r90
  text "2" at 2769.02,1032 h92.06 r90
  text "0" at 2770.68,678.18 h92.06 r90
  text "1" at 2770.68,631.56 h92.06 r90
  text "m" at 2779.01,489.59 h92.06 r90
  text "m" at 2779.01,421.33 h92.06 r90
  text "3.3V" at 1555.12,322.83 h40
  text "0" at 2773.63,267.75 h92.06 r90
M1 Board Outline:
  the board outline again, w10
  text ".Layer_Name" at 577,-858.49 h60
M2 Board Dimensions:
  rectangle: 0,-275 125,-150
  rectangle: 125,-400 500,-275
  lines w7: 0,-275 1000,-275 ; 125,-400 125,-150 ; 250,-400 250,-150 ; 500,-400 500,-150 ; 750,-400 750,-150 ; 0,-400 1000,-400 1000,-150 0,-150 0,-400
  text ".Layer_Name" at 577,-858.49 h60
M3 3D STEP Top:
  text ".Layer_Name" at 577,-858.49 h60
M4 3D STEP Bottom:
  text ".Layer_Name" at 577,-858.49 h60
M5 Assembly Top:
  lines w10: -292,-930.17 6308,-930.17 ; -292,-726.83 6310,-726.83 ; -292,-523.5 -292,-1133.5 3713,-1133.5 6310,-1133.5 6310,-523.5 -291.5,-523.5 -291.5,-1133.5 1284,-1133.5 ; 2173,-1133.5 2173,-523.5 ; 3440,-726.83 3440,-523.5 ; 4280,-726.83 4280,-523.5 ; 4902,-1140 4902,-937.17
  text "COMPONENTS MARKED 'DNP' SHOULD NOT BE POPULATED." at 1153.5,-318.5 h60
  text "ASSEMBLY VARIANT:" at 1153,-434 h60
  text ".VariantName" at 2189,-434 h60
  text "PCB VIEWED FROM TOP SIDE" at -228.5,-655.67 h60
  text "BOARD #:" at 2248,-655.67 h60
  text ".PRJ_Number" at 2793.5,-655.67 h60
  text "REV:" at 3638,-655.67 h60
  text ".PCB_Rev" at 3929.5,-655.67 h60
  text "SVN REV:" at 4476,-655.67 h60
  text ".VersionControl_RevNumber" at 4982,-655.67 h60
  text "TID #:" at 2248,-859 h60
  text ".TID" at 2793.5,-859 h60
  text "PLOT NAME =" at -228.5,-1064.34 h60
  text ".plot_File_Name" at 577,-1064.34 h60
  text "GENERATED    :" at 2250,-1064.34 h60
  text ".Print_Date" at 3119.5,-1064.34 h60
  text ".Print_Time" at 3848.5,-1064.34 h60
  text "TEXAS INSTRUMENTS" at 5113,-1064.34 h60
M6 Assembly Bottom:
  lines w10: -292.5,-727.33 6309.5,-727.33 ; -290.5,-930.67 6309.5,-930.67 ; 1115.5,-1140.5 1115.5,-937.67 ; 1737.5,-727.33 1737.5,-524 ; 2577.5,-727.33 2577.5,-524 ; 3844.5,-1134 3844.5,-524 ; 4733.5,-1134 6309,-1134 6309,-524 -292.5,-524 -292.5,-1134 2304.5,-1134 6309.5,-1134 6309.5,-524
  text "COMPONENTS MARKED 'DNP' SHOULD NOT BE POPULATED." at 6102,-318 h60
  text ".VariantName" at 5058,-434 h60
  text "ASSEMBLY VARIANT:" at 6097,-434 h60
  text ".VersionControl_RevNumber" at 1035.5,-656.17 h60
  text "SVN REV:" at 1541.5,-656.17 h60
  text ".PCB_Rev" at 2088,-656.17 h60
  text "REV:" at 2379.5,-656.17 h60
  text ".PRJ_Number" at 3224,-656.17 h60
  text "BOARD #:" at 3769.5,-656.17 h60
  text "PCB VIEWED FROM BOTTOM SIDE" at 6246,-656.17 h60
  text ".TID" at 3224,-859.5 h60
  text "TID #:" at 3769.5,-859.5 h60
  text "TEXAS INSTRUMENTS" at 904.5,-1064.84 h60
  text ".Print_Time" at 2169,-1064.84 h60
  text ".Print_Date" at 2898,-1064.84 h60
  text "GENERATED    :" at 3767.5,-1064.84 h60
  text ".plot_File_Name" at 5440.5,-1064.84 h60
  text "PLOT NAME =" at 6246,-1064.84 h60
M9 Title Sheet:
  drawing of 57 lines, arcs and shapes, not listed
  text "1" at 739.84,8036.5 h70
  text "2" at 3235.5,8036.5 h70
  text "3" at 5724.84,8036.5 h70
  text "4" at 8231.51,8036.5 h70
  text "5" at 10730.5,8036.5 h70
  text "6" at 13235.5,8036.5 h70
  text "A" at -416.5,6893.5 h70
  text "A" at 14383.5,6893.5 h70
  text "B" at -416.5,4513.5 h70
  text "B" at 14383.5,4513.5 h70
  text "C" at -416.5,2138.5 h70
  text "C" at 14383.5,2138.5 h70
  text "PROJECT TITLE:" at 11343.5,277.5 h45
  text ".PRJ_Title" at 11393.5,144.17 h70
  text "DESIGNED FOR:" at 11343.5,-23.5 h45
  text ".PRJ_Customer" at 11393.5,-163.5 h70
  text "D" at -416.5,-231.5 h70
  text "D" at 14383.5,-231.5 h70
  text "FILE NAME:" at 11343.5,-323.5 h45
  text ".PCB_File_Name_No_Path" at 11393.5,-443.5 h70
  text "Texas Instruments (TI) and/or its licensors do not warrant the accuracy or completeness of this specification" at 6374,-605.34 h45
  text "ENGINEER:" at 11343.5,-613.5 h45
  text "LAYOUT BY:" at 12848.5,-613.5 h45
  text "or any information contained therein. TI and/or its licensors do not warrant that this design will meet" at 6329.01,-718 h45
  text ".PRJ_Engineer" at 11393.5,-768.49 h70
  text ".PCB_Layout" at 12899,-768.49 h70
  text "the specifications, will be suitable for your application or fit for any particular purpose, or will operate in" at 6329.01,-830.67 h45
  text ".Layer_Name" at 577,-858.49 h60
  text "ALTIUM DESIGNER VERSION:" at 12848.5,-923.5 h45
  text "an implementation. TI and/or its licensors do not warrant that the design is production worthy. You should" at 6329.01,-943.33 h45
  text "completely validate and test your design implementation to confirm the system functionality for your application." at 6374,-1056 h45
  text ".print_Scale" at 11393.5,-1056.83 h70
  text ".Application_BuildNumber" at 12899,-1056.83 h70
  text "1" at 739.84,-1263.5 h70
  text "2" at 3235.5,-1263.5 h70
  text "3" at 5724.84,-1263.5 h70
  text "4" at 8231.51,-1263.5 h70
  text "5" at 10730.5,-1263.5 h70
  text "6" at 13235.5,-1263.5 h70
M10 Fab Notes:
  drawing of 185 lines, arcs and shapes, not listed
  text "DESIGN INFORMATION" at 12381.02,5910 h60
  text "MIN. TRACK WIDTH:" at 11736.46,5730 h60
  text "8" at 12832.7,5730 h60
  text "MIL" at 12987.46,5730 h60
  text "MIN. CLEARANCE:" at 11736.46,5598 h60
  text "0.2" at 12772.7,5598 h60
  text "mm" at 12987.46,5598 h60
  text "MIN. VIA PAD SIZE:" at 11736.46,5466 h60
  text "24" at 12802.71,5466 h60
  text "MIL" at 12987.46,5466 h60
  text "0.05mm (2MIL)" at 12431.46,5324.29 h60
  text "MINIMUM ANNULAR RING" at 11407.23,5320 h60
  text "EXTERNAL" at 13139.46,5320 h60
  text "PER" at 11607.23,5202 h60
  text "IPC-D-275 CLASS 2 LEVEL C" at 11827.23,5202 h60
  text "MIL, HOLES" at 13315.46,5089.71 h60
  text "+/-" at 12923,5089 h60
  text "+/-" at 13777,5089 h60
  text "REGISTRATION TOLERANCES:" at 11407.23,5084 h60
  text "METAL" at 12607,5084 h60
  text "5" at 13183.2,5084 h60
  text "3" at 14016.2,5084 h60
  text "MIL" at 14132.46,5084 h60
  text "MATERIAL:" at 11332.46,4874.54 h60
  text "FR-4 High Tg" at 12318.9,4734.21 h60
  text "FR-408" at 11753.46,4725.64 h60
  text "X" at 12165.46,4725.64 h60
  text "OTHER" at 13241.46,4725.64 h60
  text "62 MIL (1.6mm) +/-10%" at 12073.56,4562.92 h60
  text "THICKNESS:" at 11407.23,4558.64 h60
  text "X" at 11945.4,4558.64 h60
  text "OTHER" at 13358.46,4558.64 h60
  text "TOLERANCE:" at 11407.23,4400.64 h60
  text "X" at 12246.53,4400.64 h60
  text "ANSI IPC-6012 TYPE 3 CLASS 2" at 12433.48,4400.64 h60
  text "OTHER +/-" at 12433.46,4244.64 h60
  text "BOW & TWIST:" at 11407.23,4087.64 h60
  text "X" at 12246.53,4087.64 h60
  text "ANSI IPC-6012 TYPE 3 CLASS 2" at 12433.48,4087.64 h60
  text "OTHER +/-" at 12433.46,3929.13 h60
  text "DRILLING:" at 11332.46,3790.64 h60
  text "REFERENCE:" at 11407.23,3673.64 h60
  text "X" at 12055.46,3673.64 h60
  text "AS SHOWN" at 12242.46,3673.64 h60
  text "X" at 12956.46,3673.64 h60
  text "NC_DRILL FILES" at 13093.46,3673.64 h60
  text "PTH MIN COPPER THICKNESS:" at 11407.23,3515.64 h60
  text "X" at 12757.46,3515.64 h60
  text "1MIL" at 12894.46,3515.64 h60
  text "OTHER" at 13391.46,3515.64 h60
  text "BOARD FINISH:" at 11332.46,3356.64 h60
  text "SILKSCREEN:" at 11487.68,3238.64 h60
  text "X" at 12436.46,3238.64 h60
  text "TOP" at 12562.46,3238.64 h60
  text "X" at 12946.46,3238.64 h60
  text "BOTTOM" at 13073.46,3238.64 h60
  text "SILKSCREEN COLOR:" at 11487.68,3071.64 h60
  text "X" at 12435.42,3071.64 h60
  text "WHITE" at 12562.46,3071.64 h60
  text "OTHER" at 13073.46,3071.64 h60
  text "SOLDER RESIST COLOR:" at 11487.68,2901.64 h60
  text "X" at 12055.42,2742.44 h60
  text "GREEN" at 12182.46,2742.44 h60
  text "BLUE" at 12773.46,2742.44 h60
  text "OTHER" at 13311.46,2742.44 h60
  text "IMMERSION GOLD (ENIG)" at 12393.46,2553.92 h60
  text "ENEPIG" at 13731,2550.64 h60
  text "SURFACE FINISH:" at 11332.46,2549.64 h60
  text "X" at 12206.51,2549.64 h60
  text "IMM. TIN/SILVER OR EQUIV" at 11662,2392.64 h60
  text "OTHER" at 13093.46,2392.64 h60
  text "ARRAY/PANEL:" at 11332.46,2213.64 h60
  text "CUT AND TRIM PER MECH LAYER 1" at 12393.46,2209.35 h60
  text "N.C. ROUTE" at 12393.46,2057.64 h60
  text "X" at 13072.46,2057.64 h60
  text "V. SCORE" at 13259.46,2057.64 h60
  text "CERTIFICATION:" at 11332.46,1920.64 h60
  text "MATERIALS AND WORKMANSHIP FOR ALL PCBS" at 12057.46,1920.64 h60
  text "TO MEET OR EXCEED THE REQUIREMENTS OF:" at 12057.46,1822.64 h60
  text "X" at 11683.96,1686.13 h60
  text "ANSI IPC-A-600F CLASS ->" at 11822.96,1686.13 h60
  text "X" at 13462.02,1686.13 h60
  text "2" at 13580.96,1686.14 h60
  text "1" at 13265.96,1684.64 h60
  text "3" at 13934.96,1684.64 h60
  text "X" at 11686.02,1526.64 h60
  text "UL 94V-0" at 11822.96,1526.64 h60
  text "X" at 12498.02,1526.64 h60
  text "RoHS" at 12634.96,1526.64 h60
  text "OTHER" at 13279.36,1526.64 h60
  text "PER ORDER" at 13676.42,1526.64 h60
  text "ADDITIONAL REQUIREMENTS:" at 11332.46,1385.64 h60
  text "MICROSECTION:" at 11407.23,1270.64 h60
  text "YES" at 12312.96,1270.64 h60
  text "REQUIRED" at 13174.46,1114.49 h60
  text "BARE BOARD ELEC. TEST:" at 11407.23,1111.64 h60
  text "NONE" at 12712.96,1111.64 h60
  text "X" at 13047.46,1111.64 h60
  text "PER ORDER" at 13766.46,1111.64 h60
  text "MANUFACTURER'S UL:" at 11407.23,954.64 h60
  text "RAIL" at 12572.96,950.35 h60
  text "METAL" at 13064.77,950.35 h60
  text "X" at 13440,950 h60
  text "SILK" at 13576.46,950.35 h60
  text ".Layer_Name" at 577,-858.49 h60
M11 Gerber Information:
  lines w10: -292,-930.17 6308,-930.17 ; -292,-726.83 6310,-726.83 ; -292,-523.5 -292,-1133.5 3713,-1133.5 6310,-1133.5 6310,-523.5 -291.5,-523.5 -291.5,-1133.5 1284,-1133.5 ; 2173,-1133.5 2173,-523.5 ; 3440,-726.83 3440,-523.5 ; 4280,-726.83 4280,-523.5 ; 4902,-1140 4902,-937.17
  text "ALL ARTWORK VIEWED FROM TOP SIDE" at -228.5,-655.67 h60
  text "BOARD #:" at 2248,-655.67 h60
  text ".PRJ_Number" at 2793.5,-655.67 h60
  text "REV:" at 3638,-655.67 h60
  text ".PCB_Rev" at 3929.5,-655.67 h60
  text "SVN REV:" at 4476,-655.67 h60
  text ".VersionControl_RevNumber" at 4982,-655.67 h60
  text "LAYER NAME =" at -228.5,-858.49 h60
  text "TID #:" at 2248,-859 h60
  text ".TID" at 2793.5,-859 h60
  text "PLOT NAME =" at -228.5,-1064.34 h60
  text ".plot_File_Name" at 577,-1064.34 h60
  text "GENERATED    :" at 2250,-1064.34 h60
  text ".Print_Date" at 3119.5,-1064.34 h60
  text ".Print_Time" at 3848.5,-1064.34 h60
  text "TEXAS INSTRUMENTS" at 5113,-1064.34 h60
M12 Stackup:
  drawing of 191 lines, arcs and shapes, not listed
  text "Layer" at 9790.58,7830 h60
  text "Name" at 10200.49,7830 h60
  text "Material" at 11130.23,7830 h60
  text "Thickness" at 11990,7830 h60
  text "Constant" at 12639.84,7830 h60
  text "Board Layer Stack" at 13209.7,7830 h60
  text "1" at 9790.58,7710 h60
  text "Top Overlay" at 10200.49,7710 h60
  text "2" at 9790.58,7590 h60
  text "Top Solder" at 10200.49,7590 h60
  text "Solder Resist" at 11130.23,7590 h60
  text "0.40mil" at 11990,7590 h60
  text "3.5" at 12639.84,7590 h60
  text "3" at 9790.58,7470 h60
  text "Top Layer" at 10200.49,7470 h60
  text "Copper" at 11130.23,7470 h60
  text "1.40mil" at 11990,7470 h60
  text "4" at 9790.58,7350 h60
  text "Dielectric1" at 10200.49,7350 h60
  text "FR-4" at 11130.23,7350 h60
  text "59.20mil" at 11990,7350 h60
  text "4.8" at 12639.84,7350 h60
  text "5" at 9790.58,7230 h60
  text "Bottom Layer" at 10200.49,7230 h60
  text "Copper" at 11130.23,7230 h60
  text "1.40mil" at 11990,7230 h60
  text "6" at 9790.58,7110 h60
  text "Bottom Solder" at 10200.49,7110 h60
  text "Solder Resist" at 11130.23,7110 h60
  text "0.40mil" at 11990,7110 h60
  text "3.5" at 12639.84,7110 h60
  text "7" at 9790.58,6990 h60
  text "Bottom Overlay" at 10200.49,6990 h60
  text ".Layer_Name" at 577,-858.49 h60
M13 Component Bodies Top:
  text ".Layer_Name" at 577,-858.49 h60
M14 Component Bodies Bottom:
  text ".Layer_Name" at 577,-858.49 h60
M15 Courtyards Top:
  text ".Layer_Name" at 577,-858.49 h60
M16 Courtyards Bottom:
  text ".Layer_Name" at 577,-858.49 h60
Drill Drawing:
  circle w1: c5557.8,3259.18 r20.74
  lines w1: 5537.05,2782.12 5578.54,2782.12 5557.8,2740.64 5537.05,2782.12 ; 5537.05,2875.46 5547.42,2875.46 5557.8,2865.09 5568.17,2875.46 5578.54,2875.46 5568.17,2885.83 5578.54,2896.2 5568.17,2896.2 5557.8,2906.57 5547.42,2896.2 5537.05,2896.2 5547.42,2885.83 5537.05,2875.46 ; 5537.05,2989.53 5557.8,2999.91 5578.54,2989.53 5568.17,3010.28 5578.54,3031.02 5557.8,3020.65 5537.05,3031.02 5547.42,3010.28 5537.05,2989.53 ; 5537.05,3124.36 5547.42,3124.36 5547.42,3113.98 5568.17,3113.98 5568.17,3124.36 5578.54,3124.36 5578.54,3145.1 5568.17,3145.1 5568.17,3155.47 5547.42,3155.47 5547.42,3145.1 5537.05,3145.1 5537.05,3124.36
  lines w12: 5480,2703.3 7509.36,2703.3 ; 5480,3325.55 7509.36,3325.55 ; 5828.16,2578.85 5828.16,3450 ; 6170.27,2578.85 6170.27,3450 ; 6817.27,2578.85 6817.27,3450 ; 7086.62,2578.85 7086.62,3450 ; 5480,2578.85 7509.36,2578.85 7509.36,3450 5480,3450 5480,2578.85
  text "Symbol" at 5554.67,3362.89 h72
  text "Quantity" at 5865.5,3362.89 h72
  text "Finished Hole Size" at 6207.6,3362.89 h72
  text "Plated" at 6854.6,3362.89 h72
  text "Hole Type" at 7123.95,3362.89 h72
  text "1" at 5865.5,3238.44 h60
  text "13.00mil (0.330mm)" at 6207.6,3238.44 h60
  text "PTH" at 6854.6,3238.44 h60
  text "Round" at 7123.95,3238.44 h60
  text "27" at 5865.5,3113.98 h60
  text "15.00mil (0.381mm)" at 6207.6,3113.98 h60
  text "PTH" at 6854.6,3113.98 h60
  text "Round" at 7123.95,3113.98 h60
  text "2" at 5865.5,2989.53 h60
  text "40.00mil (1.016mm)" at 6207.6,2989.53 h60
  text "PTH" at 6854.6,2989.53 h60
  text "Round" at 7123.95,2989.53 h60
  text "18" at 5865.5,2865.09 h60
  text "40.16mil (1.020mm)" at 6207.6,2865.09 h60
  text "PTH" at 6854.6,2865.09 h60
  text "Round" at 7123.95,2865.09 h60
  text "40" at 5865.5,2740.64 h60
  text "45.28mil (1.150mm)" at 6207.6,2740.64 h60
  text "PTH" at 6854.6,2740.64 h60
  text "Round" at 7123.95,2740.64 h60
  text "88 Total" at 5865.5,2616.19 h60

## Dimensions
2300,3131.89 to 0,3149.61 on M2 Board Dimensions
0,-400 to 1000,-400 on M2 Board Dimensions
0,0 to 2650,4300 on M2 Board Dimensions
0,0 to 3600,0 on M2 Board Dimensions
